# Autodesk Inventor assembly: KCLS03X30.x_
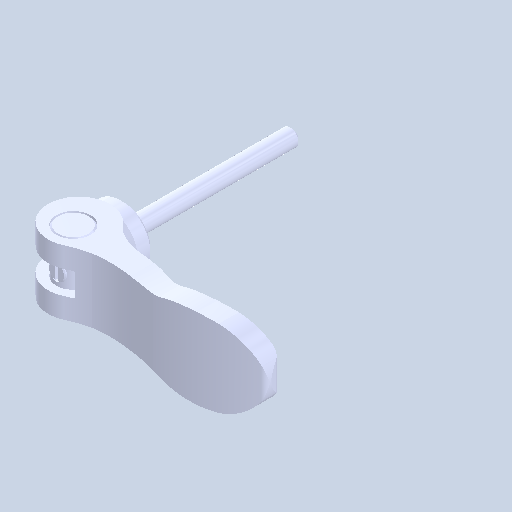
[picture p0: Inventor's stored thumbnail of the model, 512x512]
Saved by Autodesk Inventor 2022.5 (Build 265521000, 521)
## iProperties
Created: 2024-08
Part Number: KCLS03X30.x_
Document SubType Name: Assembly
Designer: ImaoCorp
Author: ImaoCorp
Sending System: SOLIDWORKS 2022-2022290
MC: AMD64
MC_MODEL: Intel64 Family 6 Model 60 Stepping 3, GenuineIntel
OS: Windows_NT
FRU: Parasolid Version 33.1, build 260,  4-25-2022
FORMAT: text
GUISE: transmit
KEY: FILEKCLS03X30.x_t
DATE: Thu Aug 29 10:53:57 2024
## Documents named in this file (5)
- Y:\5.更新分\2024年対応\1001_KCL\データ\kcls03x30\KCLS03X30.x_.iam
- Y:\5.更新分\2024年対応\1001_KCL\データ\kcls03x30\KCLS03X30_01.ipt
- Y:\5.更新分\2024年対応\1001_KCL\データ\kcls03x30\KCLS03X30_02.ipt
- Y:\5.更新分\2024年対応\1001_KCL\データ\kcls03x30\KCLS03X30_03.ipt
- Y:\5.更新分\2024年対応\1001_KCL\データ\kcls03x30\KCLS03X30_04.ipt
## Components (4 placed, 4 different names)
1. KCLS03X30_01
2. KCLS03X30_02
3. KCLS03X30_03
4. KCLS03X30_04
